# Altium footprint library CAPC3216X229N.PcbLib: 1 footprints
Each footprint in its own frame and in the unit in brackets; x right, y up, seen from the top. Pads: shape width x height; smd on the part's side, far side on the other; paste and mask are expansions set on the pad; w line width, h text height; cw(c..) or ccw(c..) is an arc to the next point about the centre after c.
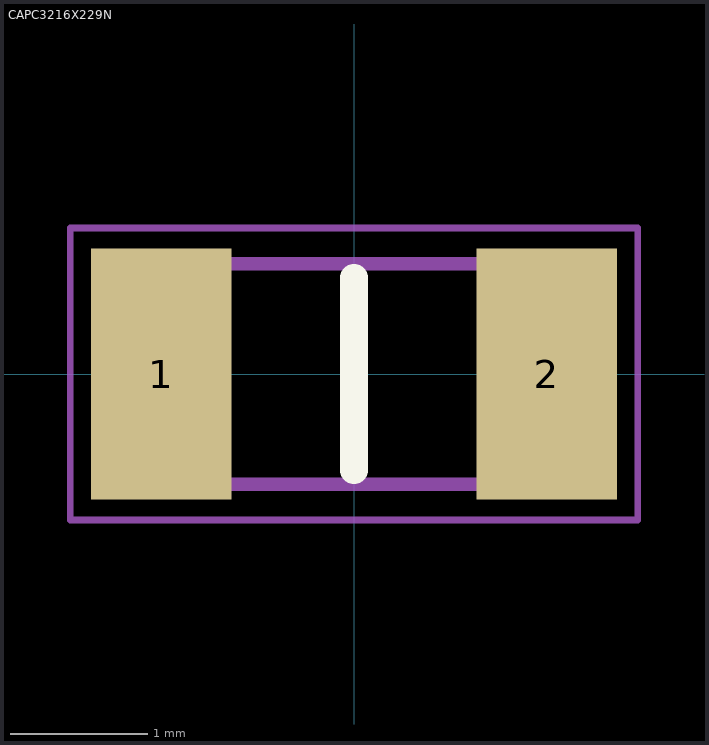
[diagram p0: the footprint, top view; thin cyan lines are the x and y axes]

## CAPC3216X229N [mm]
pads (2):
  rect 1.02x1.82 smd: 1(-1.4,0) 2(1.4,0)
Top Overlay:
  lines w0.2: 0,-0.7 0,0.7
Mechanical 15:
  lines w0.1: -1.6,-0.8 1.6,-0.8 1.6,0.8 -1.6,0.8 -1.6,-0.8
Mechanical 20:
  lines w0.05: -2.06,-1.06 2.06,-1.06 2.06,1.06 -2.06,1.06 -2.06,-1.06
